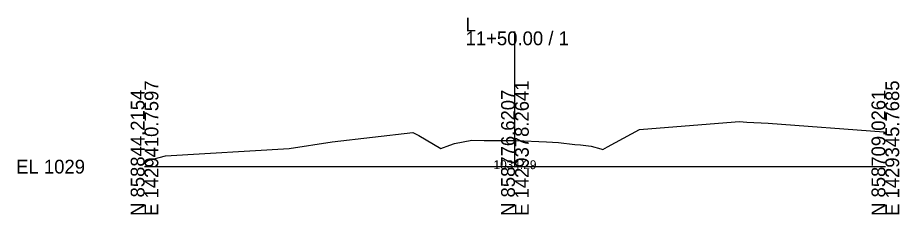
# Model space of a CAD drawing. Extents: x -26 to 176, y -10 to 13058.
# Drawn here: x -25.7 to 152.8, y -9.7 to 30.2 of the extents above; entities that cross this region are included whole.
import ezdxf

# ---------------------------------------------------------------- set-up
doc = ezdxf.new("R2010")
doc.units = 0
for name, color, linetype in [('Default', 7, 'Continuous'), ('Exist Cross Section Cell', 7, 'Continuous'), ('Exist XS Center Line Elevation Label', 7, 'Continuous'), ('Exist XS Ground Line', 7, 'Continuous')]:
    doc.layers.add(name, color=color, linetype=linetype)

msp = doc.modelspace()

# ---------------------------------------------------------------- linework, layer by layer
at = {"layer": 'Exist Cross Section Cell'}
for p, q in [((75, 0), (75, 27.44)), ((0, 0), (75, 0)), ((75, 0), (150, 0))]:
    msp.add_line(p, q, dxfattribs=at)
at = {"layer": 'Exist XS Ground Line'}
msp.add_lwpolyline([(0, 0.7), (0.66, 1.27), (4.26, 2.22), (29.28, 3.71), (37.98, 5.05), (54.3, 6.94), (55.52, 6.29), (60, 3.7), (61.85, 4.36), (62.79, 4.69), (64.49, 5.03), (66.24, 5.35), (68.78, 5.33), (75.24, 5.29), (81.38, 5.02), (83.84, 4.93), (87.13, 4.51), (88.28, 4.41), (90.43, 4.15), (92.39, 3.58), (92.8, 3.47), (93.73, 3.99), (100.25, 7.55), (119.58, 9.11), (120.44, 9.15), (121.96, 9.02), (126.29, 8.83), (149.69, 7.03), (150, 7)], dxfattribs=at)
msp.add_lwpolyline([(0, 0.7), (0.66, 1.27), (4.26, 2.22), (29.28, 3.71), (37.98, 5.05), (54.3, 6.94), (55.52, 6.29), (60, 3.7), (61.85, 4.36), (62.79, 4.69), (64.49, 5.03), (66.24, 5.35), (68.78, 5.33), (75.24, 5.29), (81.38, 5.02), (83.84, 4.93), (87.13, 4.51), (88.28, 4.41), (90.43, 4.15), (92.39, 3.58), (92.8, 3.47), (93.73, 3.99), (100.25, 7.55), (119.58, 9.11), (120.44, 9.15), (121.96, 9.02), (126.29, 8.83), (149.69, 7.03), (150, 7)], dxfattribs=at)
msp.add_lwpolyline([(0, 0.7), (0.66, 1.27), (4.26, 2.22), (29.28, 3.71), (37.98, 5.05), (54.3, 6.94), (55.52, 6.29), (60, 3.7), (61.85, 4.36), (62.79, 4.69), (64.49, 5.03), (66.24, 5.35), (68.78, 5.33), (75.24, 5.29), (81.38, 5.02), (83.84, 4.93), (87.13, 4.51), (88.28, 4.41), (90.43, 4.15), (92.39, 3.58), (92.8, 3.47), (93.73, 3.99), (100.25, 7.55), (119.58, 9.11), (120.44, 9.15), (121.96, 9.02), (126.29, 8.83), (149.69, 7.03), (150, 7)], dxfattribs=at)

# ---------------------------------------------------------------- texts
at = {"layer": 'Default'}
msp.add_text('-', height=0.0001, dxfattribs=at).set_placement((0, 0))
at = {"layer": 'Exist Cross Section Cell'}
for s, p in [('L', (65, 27.44)), ('11+50.00 / 1', (65, 24.64)), ('EL 1029', (-26, -1.4))]:
    msp.add_text(s, height=2.8, dxfattribs=at).set_placement(p)
for s, p in [('E 1429410.7597', (2.8, -10)), ('E 1429378.2641', (77.8, -10)), ('E 1429345.7685', (152.8, -10)), ('N 858844.2154', (0, -10)), ('N 858776.6207', (75, -10)), ('N 858709.0261', (150, -10))]:
    msp.add_text(s, height=2.8, rotation=90, dxfattribs=at).set_placement(p)
at = {"layer": 'Exist XS Center Line Elevation Label'}
msp.add_text('1034.29', height=1.8, dxfattribs=at).set_placement((70.66, -0.51))
msp.add_text('1034.29', height=1.8, dxfattribs=at).set_placement((70.66, -0.51))
msp.add_text('1034.29', height=1.8, dxfattribs=at).set_placement((70.66, -0.51))

doc.saveas('drawing.dxf')
